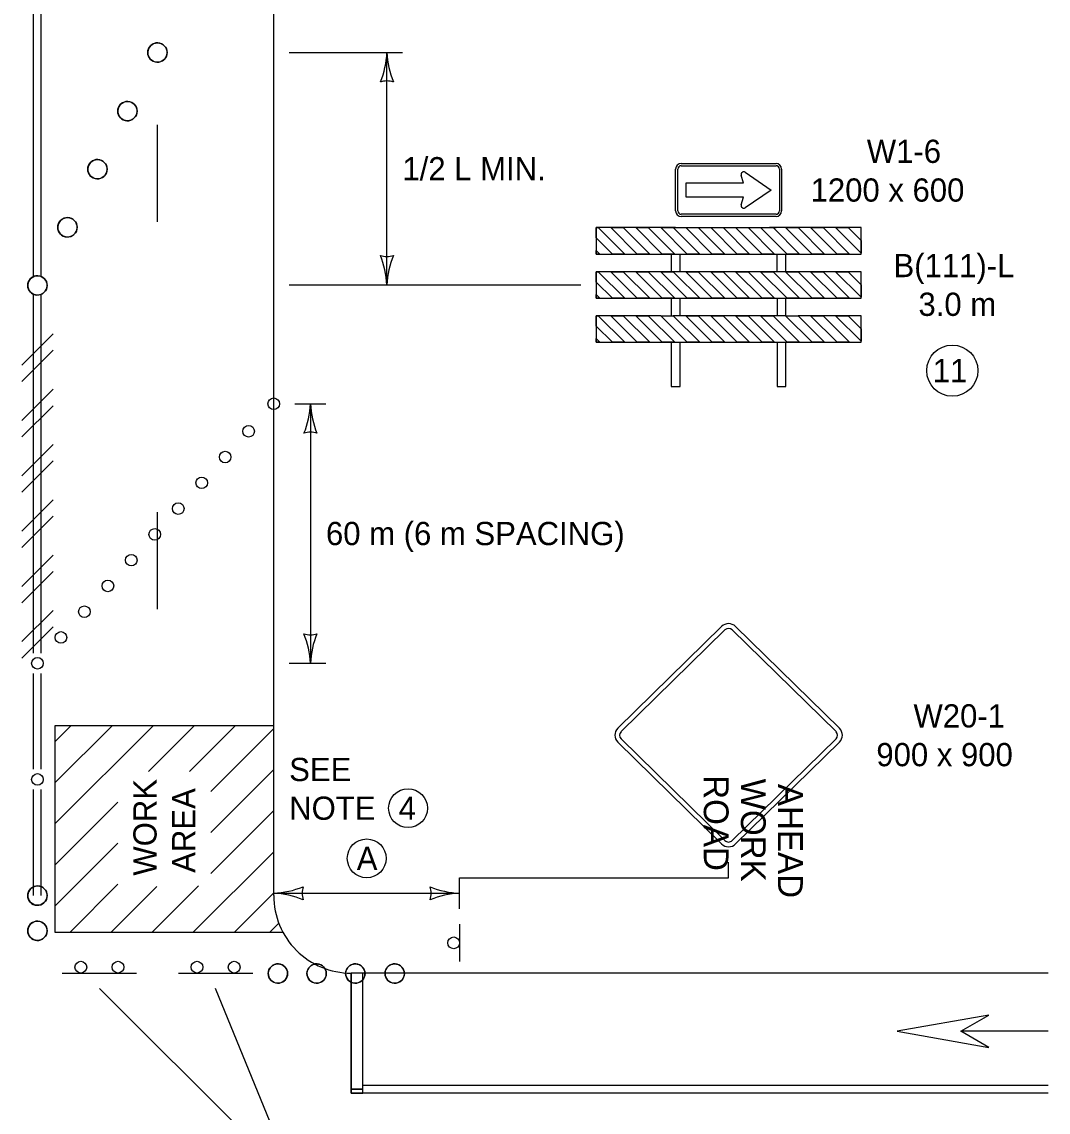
# Model space of a CAD drawing. Extents: x 49991.4 to 50021, y 49987.6 to 50011.4.
# Drawn here: x 50010.553 to 50013.203, y 49993.381 to 49996.197 of the extents above; entities that cross this region are included whole.
import ezdxf

# ---------------------------------------------------------------- set-up
doc = ezdxf.new("R2010")
doc.units = 0
for name, color, linetype in [('Level 1', 7, 'Continuous'), ('Level 2', 7, 'Continuous'), ('Level 3', 7, 'Continuous')]:
    doc.layers.add(name, color=color, linetype=linetype)

# ---------------------------------------------------------------- blocks, each defined once
blk = doc.blocks.new('ARR')
at = {"layer": 'Level 3'}
for centre, radius, start, end in [((1.53, 37.02), 37.05, 247.456, 267.6395), ((-21.37, 0), 9.13, 342.1388, 17.8612), ((1.92, -38.79), 38.83, 92.8273, 112.0772)]:
    blk.add_arc(centre, radius, start, end, dxfattribs=at)

msp = doc.modelspace()

# ---------------------------------------------------------------- linework, layer by layer
at = {"layer": 'Level 1'}
for p, q in [((50011.2032, 49993.9404), (50011.2032, 49998.6295)), ((50010.5832, 49995.5402), (50010.5832, 49996.4525)), ((50010.6032, 49995.5402), (50010.6032, 49996.4525)), ((50010.9033, 49995.6804), (50010.9033, 49995.9304)), ((50012.2411, 49995.7082), (50012.2411, 49995.8165)), ((50012.2468, 49995.7082), (50012.2468, 49995.8165)), ((50012.2554, 49995.8307), (50012.5004, 49995.8307)), ((50012.2554, 49995.825), (50012.5004, 49995.825)), ((50012.509, 49995.8165), (50012.509, 49995.7082)), ((50012.5147, 49995.8165), (50012.5147, 49995.7082)), ((50012.4168, 49995.7806), (50012.4104, 49995.8002)), ((50012.4209, 49995.808), (50012.4874, 49995.7623)), ((50012.2684, 49995.7441), (50012.2684, 49995.7806)), ((50012.2684, 49995.7806), (50012.4168, 49995.7806)), ((50012.4874, 49995.7623), (50012.4209, 49995.7166)), ((50012.4066, 49995.7441), (50012.2684, 49995.7441)), ((50012.4168, 49995.7441), (50012.4066, 49995.7441)), ((50012.4104, 49995.7245), (50012.4168, 49995.7441)), ((50012.5004, 49995.6996), (50012.2554, 49995.6996)), ((50012.5004, 49995.6939), (50012.2554, 49995.6939)), ((50012.1099, 49995.597), (50012.0415, 49995.6654)), ((50012.0415, 49995.6654), (50012.1099, 49995.597)), ((50012.1422, 49995.597), (50012.0738, 49995.6654)), ((50012.1422, 49995.597), (50012.0738, 49995.6654)), ((50012.1744, 49995.597), (50012.106, 49995.6654)), ((50012.106, 49995.6654), (50012.1744, 49995.597)), ((50012.2066, 49995.597), (50012.1382, 49995.6654)), ((50012.2066, 49995.597), (50012.1382, 49995.6654)), ((50012.2389, 49995.597), (50012.1705, 49995.6654)), ((50012.1705, 49995.6654), (50012.2389, 49995.597)), ((50012.2712, 49995.597), (50012.2028, 49995.6654)), ((50012.3034, 49995.597), (50012.235, 49995.6654)), ((50012.235, 49995.6654), (50012.2749, 49995.6654)), ((50012.2554, 49995.6654), (50012.5004, 49995.6654)), ((50012.3356, 49995.597), (50012.2672, 49995.6654)), ((50012.3678, 49995.597), (50012.2994, 49995.6654)), ((50012.4, 49995.597), (50012.3316, 49995.6654)), ((50012.4322, 49995.597), (50012.3638, 49995.6654)), ((50012.4644, 49995.597), (50012.396, 49995.6654)), ((50012.4966, 49995.597), (50012.4282, 49995.6654)), ((50012.529, 49995.597), (50012.4606, 49995.6654)), ((50012.5147, 49995.6654), (50012.4834, 49995.6654)), ((50012.5613, 49995.597), (50012.4929, 49995.6654)), ((50012.5935, 49995.597), (50012.5251, 49995.6654)), ((50012.5935, 49995.597), (50012.5251, 49995.6654)), ((50012.6257, 49995.597), (50012.5573, 49995.6654)), ((50012.5573, 49995.6654), (50012.6257, 49995.597)), ((50012.658, 49995.597), (50012.5896, 49995.6654)), ((50012.658, 49995.597), (50012.5896, 49995.6654)), ((50012.6902, 49995.597), (50012.6218, 49995.6654)), ((50012.6218, 49995.6654), (50012.6902, 49995.597)), ((50012.7199, 49995.5996), (50012.654, 49995.6654)), ((50012.7199, 49995.5996), (50012.654, 49995.6654)), ((50012.7199, 49995.6319), (50012.6863, 49995.6654)), ((50012.6863, 49995.6654), (50012.7199, 49995.6319)), ((50012.0777, 49995.597), (50012.0359, 49995.6388)), ((50012.0777, 49995.597), (50012.0359, 49995.6388)), ((50012.0455, 49995.597), (50012.0359, 49995.6065)), ((50012.0359, 49995.6065), (50012.0455, 49995.597)), ((50012.2525, 49995.5515), (50012.2525, 49995.597)), ((50012.5033, 49995.5515), (50012.5033, 49995.597)), ((50012.1099, 49995.4831), (50012.0415, 49995.5515)), ((50012.0415, 49995.5515), (50012.1099, 49995.4831)), ((50012.1422, 49995.4831), (50012.0738, 49995.5515)), ((50012.1422, 49995.4831), (50012.0738, 49995.5515)), ((50012.1744, 49995.4831), (50012.106, 49995.5515)), ((50012.106, 49995.5515), (50012.1744, 49995.4831)), ((50012.2066, 49995.4831), (50012.1382, 49995.5515)), ((50012.2066, 49995.4831), (50012.1382, 49995.5515)), ((50012.2389, 49995.4831), (50012.1705, 49995.5515)), ((50012.1705, 49995.5515), (50012.2389, 49995.4831)), ((50012.2411, 49995.5131), (50012.2028, 49995.5515)), ((50012.2411, 49995.5453), (50012.235, 49995.5515)), ((50012.3034, 49995.4831), (50012.2411, 49995.5453)), ((50012.3356, 49995.4831), (50012.2672, 49995.5515)), ((50012.3678, 49995.4831), (50012.2994, 49995.5515)), ((50012.4001, 49995.4831), (50012.3317, 49995.5515)), ((50012.4323, 49995.4831), (50012.3639, 49995.5515)), ((50012.4645, 49995.4831), (50012.3961, 49995.5515)), ((50012.4968, 49995.4831), (50012.4284, 49995.5515)), ((50012.529, 49995.4831), (50012.4606, 49995.5515)), ((50012.5613, 49995.4831), (50012.4929, 49995.5515)), ((50012.5935, 49995.4831), (50012.5251, 49995.5515)), ((50012.5935, 49995.4831), (50012.5251, 49995.5515)), ((50012.6257, 49995.4831), (50012.5573, 49995.5515)), ((50012.5573, 49995.5515), (50012.6257, 49995.4831)), ((50012.658, 49995.4831), (50012.5896, 49995.5515)), ((50012.658, 49995.4831), (50012.5896, 49995.5515)), ((50012.6902, 49995.4831), (50012.6218, 49995.5515)), ((50012.6218, 49995.5515), (50012.6902, 49995.4831)), ((50012.7199, 49995.4857), (50012.654, 49995.5515)), ((50012.7199, 49995.4857), (50012.654, 49995.5515)), ((50012.7199, 49995.5179), (50012.6863, 49995.5515)), ((50012.6863, 49995.5515), (50012.7199, 49995.5179)), ((50012.0777, 49995.4831), (50012.0359, 49995.5248)), ((50012.0777, 49995.4831), (50012.0359, 49995.5248)), ((50012.2712, 49995.4831), (50012.2411, 49995.5131)), ((50010.5832, 49994.5666), (50010.5832, 49995.4931)), ((50010.6032, 49994.5666), (50010.6032, 49995.4931)), ((50012.0455, 49995.4831), (50012.0359, 49995.4926)), ((50012.0359, 49995.4926), (50012.0455, 49995.4831)), ((50012.1099, 49995.3692), (50012.0415, 49995.4376)), ((50012.0415, 49995.4376), (50012.1099, 49995.3692)), ((50012.1422, 49995.3692), (50012.0738, 49995.4376)), ((50012.1422, 49995.3692), (50012.0738, 49995.4376)), ((50012.1744, 49995.3692), (50012.106, 49995.4376)), ((50012.106, 49995.4376), (50012.1744, 49995.3692)), ((50012.2066, 49995.3692), (50012.1382, 49995.4376)), ((50012.2066, 49995.3692), (50012.1382, 49995.4376)), ((50012.2389, 49995.3692), (50012.1705, 49995.4376)), ((50012.1705, 49995.4376), (50012.2389, 49995.3692)), ((50012.2712, 49995.3692), (50012.2028, 49995.4376)), ((50012.2712, 49995.3692), (50012.2028, 49995.4376)), ((50012.3034, 49995.3692), (50012.235, 49995.4376)), ((50012.235, 49995.4376), (50012.3034, 49995.3692)), ((50012.3356, 49995.3692), (50012.2672, 49995.4376)), ((50012.3356, 49995.3692), (50012.2672, 49995.4376)), ((50012.3678, 49995.3692), (50012.2994, 49995.4376)), ((50012.2994, 49995.4376), (50012.3678, 49995.3692)), ((50012.4001, 49995.3692), (50012.3317, 49995.4376)), ((50012.4001, 49995.3692), (50012.3317, 49995.4376)), ((50012.4323, 49995.3692), (50012.3639, 49995.4376)), ((50012.3639, 49995.4376), (50012.4323, 49995.3692)), ((50012.4645, 49995.3692), (50012.3961, 49995.4376)), ((50012.4645, 49995.3692), (50012.3961, 49995.4376)), ((50012.4968, 49995.3692), (50012.4284, 49995.4376)), ((50012.4284, 49995.4376), (50012.4968, 49995.3692)), ((50012.529, 49995.3692), (50012.4606, 49995.4376)), ((50012.529, 49995.3692), (50012.4606, 49995.4376)), ((50012.5613, 49995.3692), (50012.4929, 49995.4376)), ((50012.4929, 49995.4376), (50012.5613, 49995.3692)), ((50012.5935, 49995.3692), (50012.5251, 49995.4376)), ((50012.5935, 49995.3692), (50012.5251, 49995.4376)), ((50012.6257, 49995.3692), (50012.5573, 49995.4376)), ((50012.5573, 49995.4376), (50012.6257, 49995.3692)), ((50012.658, 49995.3692), (50012.5896, 49995.4376)), ((50012.658, 49995.3692), (50012.5896, 49995.4376)), ((50012.6902, 49995.3692), (50012.6218, 49995.4376)), ((50012.6218, 49995.4376), (50012.6902, 49995.3692)), ((50012.7199, 49995.3717), (50012.654, 49995.4376)), ((50012.7199, 49995.3717), (50012.654, 49995.4376)), ((50012.7199, 49995.4039), (50012.6863, 49995.4376)), ((50012.6863, 49995.4376), (50012.7199, 49995.4039)), ((50010.5528, 49995.3104), (50010.6336, 49995.3912)), ((50012.0777, 49995.3692), (50012.0359, 49995.4109)), ((50012.0777, 49995.3692), (50012.0359, 49995.4109)), ((50012.0455, 49995.3692), (50012.0359, 49995.3787)), ((50012.0359, 49995.3787), (50012.0455, 49995.3692)), ((50010.5528, 49995.2676), (50010.6336, 49995.3484)), ((50010.5528, 49995.1676), (50010.6336, 49995.2484)), ((50010.5528, 49995.1247), (50010.6336, 49995.2055)), ((50010.5528, 49995.0247), (50010.6336, 49995.1055)), ((50010.5528, 49994.9819), (50010.6336, 49995.0627)), ((50010.5528, 49994.8819), (50010.6336, 49994.9627)), ((50010.5528, 49994.839), (50010.6336, 49994.9198)), ((50010.9033, 49994.6804), (50010.9033, 49994.9304)), ((50010.5528, 49994.739), (50010.6336, 49994.8198)), ((50010.5528, 49994.6962), (50010.6336, 49994.777)), ((50010.5528, 49994.5962), (50010.6336, 49994.677)), ((50010.5528, 49994.5533), (50010.6336, 49994.6341)), ((50012.0917, 49994.3726), (50012.3599, 49994.6354)), ((50012.3958, 49994.6354), (50012.6641, 49994.3726)), ((50012.1003, 49994.3638), (50012.3685, 49994.6266)), ((50012.3872, 49994.6266), (50012.6555, 49994.3638)), ((50010.5832, 49994.2666), (50010.5832, 49994.5142)), ((50010.6032, 49994.2666), (50010.6032, 49994.5142)), ((50011.2032, 49994.3789), (50010.6384, 49994.3789)), ((50010.6384, 49994.3789), (50010.6384, 49993.8464)), ((50010.6384, 49994.3377), (50010.6796, 49994.3789)), ((50010.6384, 49994.2316), (50010.7857, 49994.3789)), ((50010.6384, 49994.1255), (50010.8918, 49994.3789)), ((50010.88, 49994.2611), (50010.9978, 49994.3789)), ((50010.9861, 49994.2611), (50011.1039, 49994.3789)), ((50011.0408, 49994.2097), (50011.2032, 49994.3721)), ((50012.3599, 49994.0738), (50012.0917, 49994.3366)), ((50012.3685, 49994.0826), (50012.1003, 49994.3454)), ((50012.6555, 49994.3454), (50012.3872, 49994.0826)), ((50012.6641, 49994.3366), (50012.3958, 49994.0738)), ((50011.0408, 49994.1037), (50011.2032, 49994.2661)), ((50010.5832, 49993.9404), (50010.5832, 49994.2142)), ((50010.6032, 49993.9404), (50010.6032, 49994.2142)), ((50010.6384, 49994.0195), (50010.8008, 49994.1819)), ((50011.0408, 49993.9976), (50011.2032, 49994.16)), ((50010.6384, 49993.9134), (50010.8008, 49994.0758)), ((50010.9957, 49993.8464), (50011.2032, 49994.0539)), ((50010.6775, 49993.8464), (50010.8008, 49993.9697)), ((50010.7836, 49993.8464), (50010.9014, 49993.9643)), ((50010.8896, 49993.8464), (50011.0091, 49993.9659)), ((50011.1017, 49993.8464), (50011.2032, 49993.9479)), ((50010.6384, 49993.8464), (50011.2266, 49993.8464)), ((50011.1936, 49993.8464), (50011.2163, 49993.8691)), ((50011.6832, 49993.8665), (50011.6832, 49993.7705)), ((50010.6572, 49993.7405), (50010.7532, 49993.7405)), ((50010.7532, 49993.7405), (50010.8492, 49993.7405)), ((50010.9572, 49993.7405), (50011.0532, 49993.7405)), ((50011.0532, 49993.7405), (50011.1492, 49993.7405)), ((50013.2032, 49993.7404), (50011.4032, 49993.7404)), ((50011.4032, 49993.4304), (50011.4032, 49993.7404)), ((50011.4332, 49993.4304), (50011.4332, 49993.7404)), ((50013.2032, 49993.5905), (50012.9773, 49993.5905)), ((50013.2032, 49993.5901), (50012.9773, 49993.5901)), ((50013.2032, 49993.4504), (50011.4332, 49993.4504)), ((50011.4332, 49993.4405), (50011.4032, 49993.4405)), ((50013.2032, 49993.4304), (50011.4032, 49993.4304))]:
    msp.add_line(p, q, dxfattribs=at)
for points in [[(50012.2411, 49995.6654), (50012.0359, 49995.6654), (50012.0359, 49995.597), (50012.2411, 49995.597)], [(50012.0359, 49995.6388), (50012.0359, 49995.6654), (50012.0415, 49995.6654)], [(50012.0738, 49995.6654), (50012.106, 49995.6654)], [(50012.1382, 49995.6654), (50012.1705, 49995.6654)], [(50012.3034, 49995.597), (50012.2712, 49995.597), (50012.2028, 49995.6654), (50012.235, 49995.6654), (50012.3034, 49995.597)], [(50012.2411, 49995.597), (50012.7199, 49995.597), (50012.7199, 49995.6654), (50012.5147, 49995.6654)], [(50012.2672, 49995.6654), (50012.2749, 49995.6654), (50012.2994, 49995.6654), (50012.3678, 49995.597), (50012.3356, 49995.597), (50012.2672, 49995.6654)], [(50012.3316, 49995.6654), (50012.3638, 49995.6654), (50012.4322, 49995.597), (50012.4, 49995.597), (50012.3316, 49995.6654)], [(50012.396, 49995.6654), (50012.4282, 49995.6654), (50012.4966, 49995.597), (50012.4644, 49995.597), (50012.396, 49995.6654)], [(50012.4606, 49995.6654), (50012.4834, 49995.6654), (50012.4929, 49995.6654), (50012.5613, 49995.597), (50012.529, 49995.597), (50012.4606, 49995.6654)], [(50012.5251, 49995.6654), (50012.5573, 49995.6654)], [(50012.5896, 49995.6654), (50012.6218, 49995.6654)], [(50012.654, 49995.6654), (50012.6863, 49995.6654)], [(50012.7199, 49995.6319), (50012.7199, 49995.5996)], [(50012.0455, 49995.597), (50012.0359, 49995.597), (50012.0359, 49995.6065)], [(50012.1099, 49995.597), (50012.0777, 49995.597)], [(50012.1744, 49995.597), (50012.1422, 49995.597)], [(50012.2389, 49995.597), (50012.2066, 49995.597)], [(50012.2297, 49995.597), (50012.2297, 49995.5515)], [(50012.5261, 49995.5514), (50012.5261, 49995.597)], [(50012.6257, 49995.597), (50012.5935, 49995.597)], [(50012.6902, 49995.597), (50012.658, 49995.597)], [(50012.2411, 49995.5515), (50012.0359, 49995.5515), (50012.0359, 49995.4831), (50012.7199, 49995.4831), (50012.7199, 49995.5515), (50012.2411, 49995.5515)], [(50012.0359, 49995.5248), (50012.0359, 49995.5515), (50012.0415, 49995.5515)], [(50012.0738, 49995.5515), (50012.106, 49995.5515)], [(50012.1382, 49995.5515), (50012.1705, 49995.5515)], [(50012.3034, 49995.4831), (50012.2712, 49995.4831), (50012.2411, 49995.5131), (50012.2028, 49995.5515), (50012.2297, 49995.5515), (50012.235, 49995.5515), (50012.2411, 49995.5453), (50012.3034, 49995.4831)], [(50012.2672, 49995.5515), (50012.2994, 49995.5515), (50012.3678, 49995.4831), (50012.3356, 49995.4831), (50012.2672, 49995.5515)], [(50012.3317, 49995.5515), (50012.3639, 49995.5515), (50012.4323, 49995.4831), (50012.4001, 49995.4831), (50012.3317, 49995.5515)], [(50012.3961, 49995.5515), (50012.4284, 49995.5515), (50012.4968, 49995.4831), (50012.4645, 49995.4831), (50012.3961, 49995.5515)], [(50012.4606, 49995.5515), (50012.4929, 49995.5515), (50012.5613, 49995.4831), (50012.529, 49995.4831), (50012.4606, 49995.5515)], [(50012.5251, 49995.5515), (50012.5573, 49995.5515)], [(50012.5896, 49995.5515), (50012.6218, 49995.5515)], [(50012.654, 49995.5515), (50012.6863, 49995.5515)], [(50012.7199, 49995.5179), (50012.7199, 49995.4857)], [(50012.0455, 49995.4831), (50012.0359, 49995.4831), (50012.0359, 49995.4926)], [(50012.1099, 49995.4831), (50012.0777, 49995.4831)], [(50012.1744, 49995.4831), (50012.1422, 49995.4831)], [(50012.2389, 49995.4831), (50012.2066, 49995.4831)], [(50012.2297, 49995.4831), (50012.2297, 49995.4376)], [(50012.2525, 49995.4376), (50012.2525, 49995.4831)], [(50012.5033, 49995.4831), (50012.5033, 49995.4376)], [(50012.5261, 49995.4376), (50012.5261, 49995.4831)], [(50012.6257, 49995.4831), (50012.5935, 49995.4831)], [(50012.6902, 49995.4831), (50012.658, 49995.4831)], [(50012.0359, 49995.4109), (50012.0359, 49995.4376), (50012.0415, 49995.4376)], [(50012.2028, 49995.4376), (50012.0359, 49995.4376), (50012.0359, 49995.3692), (50012.7199, 49995.3692), (50012.7199, 49995.4376), (50012.5573, 49995.4376)], [(50012.0738, 49995.4376), (50012.106, 49995.4376)], [(50012.1382, 49995.4376), (50012.1705, 49995.4376)], [(50012.2028, 49995.4376), (50012.235, 49995.4376)], [(50012.5251, 49995.4376), (50012.235, 49995.4376)], [(50012.2672, 49995.4376), (50012.2994, 49995.4376)], [(50012.3317, 49995.4376), (50012.3639, 49995.4376)], [(50012.3961, 49995.4376), (50012.4284, 49995.4376)], [(50012.4606, 49995.4376), (50012.4929, 49995.4376)], [(50012.5251, 49995.4376), (50012.5573, 49995.4376)], [(50012.5896, 49995.4376), (50012.6218, 49995.4376)], [(50012.654, 49995.4376), (50012.6863, 49995.4376)], [(50012.7199, 49995.4039), (50012.7199, 49995.3717)], [(50012.0455, 49995.3692), (50012.0359, 49995.3692), (50012.0359, 49995.3787)], [(50012.1099, 49995.3692), (50012.0777, 49995.3692)], [(50012.1744, 49995.3692), (50012.1422, 49995.3692)], [(50012.2389, 49995.3692), (50012.2066, 49995.3692)], [(50012.2297, 49995.369), (50012.2297, 49995.2551), (50012.2525, 49995.2551), (50012.2525, 49995.369)], [(50012.3034, 49995.3692), (50012.2712, 49995.3692)], [(50012.3678, 49995.3692), (50012.3356, 49995.3692)], [(50012.4323, 49995.3692), (50012.4001, 49995.3692)], [(50012.4968, 49995.3692), (50012.4645, 49995.3692)], [(50012.5033, 49995.369), (50012.5033, 49995.2551), (50012.5261, 49995.2551), (50012.5261, 49995.369)], [(50012.5613, 49995.3692), (50012.529, 49995.3692)], [(50012.6257, 49995.3692), (50012.5935, 49995.3692)], [(50012.6902, 49995.3692), (50012.658, 49995.3692)], [(50011.4332, 49993.7404), (50011.4032, 49993.7404), (50011.4032, 49993.4405), (50011.4332, 49993.4405), (50011.4332, 49993.7404)], [(50011.4032, 49993.4405), (50011.4032, 49993.4304), (50011.4332, 49993.4304), (50011.4332, 49993.4405), (50011.4032, 49993.4405)]]:
    msp.add_lwpolyline(points, dxfattribs=at)
msp.add_lwpolyline([(50013.0496, 49993.6321), (50012.8131, 49993.5905), (50013.0496, 49993.5485), (50012.9774, 49993.5905)], close=True, dxfattribs=at)
for centre, radius in [((50010.903, 49996.1173), 0.025), ((50010.8256, 49995.966), 0.025), ((50010.7481, 49995.816), 0.025), ((50010.6706, 49995.666), 0.025), ((50010.5932, 49995.516), 0.025), ((50011.2032, 49995.2104), 0.015), ((50011.1385, 49995.1394), 0.015), ((50011.0779, 49995.0728), 0.015), ((50011.0173, 49995.0063), 0.015), ((50010.9567, 49994.9397), 0.015), ((50010.8961, 49994.8732), 0.015), ((50010.8355, 49994.8066), 0.015), ((50010.775, 49994.7401), 0.015), ((50010.7144, 49994.6735), 0.015), ((50010.6538, 49994.607), 0.015), ((50010.5932, 49994.5404), 0.015), ((50010.5932, 49994.2404), 0.015), ((50010.5932, 49993.9404), 0.025), ((50010.5932, 49993.8496), 0.025), ((50011.668, 49993.8185), 0.0152), ((50010.7052, 49993.7557), 0.0152), ((50010.8012, 49993.7557), 0.0152), ((50011.0052, 49993.7557), 0.0152), ((50011.1012, 49993.7557), 0.0152), ((50011.2141, 49993.7392), 0.025), ((50011.3141, 49993.7392), 0.025), ((50011.414, 49993.7392), 0.025), ((50011.5157, 49993.7392), 0.025)]:
    msp.add_circle(centre, radius, dxfattribs=at)
for centre, radius, start, end in [((50010.903, 49996.1173), 0.025, 357.0759, 177.0759), ((50010.903, 49996.1173), 0.025, 177.0759, 357.0759), ((50010.8256, 49995.966), 0.025, 357.0759, 177.0759), ((50010.8256, 49995.966), 0.025, 177.0759, 357.0759), ((50010.7481, 49995.816), 0.025, 177.0759, 357.0759), ((50010.7481, 49995.816), 0.025, 357.0759, 177.0759), ((50012.2554, 49995.8165), 0.0142, 90, 180), ((50012.2554, 49995.8165), 0.00855, 90, 180), ((50012.5004, 49995.8165), 0.0142, 0, 90), ((50012.5004, 49995.8165), 0.00855, 0, 90), ((50012.417, 49995.8023), 0.00695, 55.4806, 197.9582), ((50012.2554, 49995.7082), 0.0142, 180, 270), ((50012.2554, 49995.7082), 0.00855, 180, 270), ((50012.417, 49995.7224), 0.00695, 162.0418, 304.5194), ((50012.5004, 49995.7082), 0.0142, 270, 0), ((50012.5004, 49995.7082), 0.00855, 270, 0), ((50010.6706, 49995.666), 0.025, 357.0759, 177.0759), ((50010.6706, 49995.666), 0.025, 177.0759, 357.0759), ((50010.5932, 49995.516), 0.025, 357.0759, 177.0759), ((50010.5932, 49995.516), 0.025, 177.0759, 357.0759), ((50010.5932, 49993.9404), 0.025, 357.0759, 177.0759), ((50010.5932, 49993.9404), 0.025, 177.0759, 357.0759), ((50011.4032, 49993.9404), 0.2, 180, 270.0006), ((50010.5932, 49993.8496), 0.025, 357.0759, 177.0759), ((50010.5932, 49993.8496), 0.025, 177.0759, 357.0759), ((50011.2141, 49993.7392), 0.025, 357.0759, 177.0759), ((50011.3141, 49993.7392), 0.025, 357.0759, 177.0759), ((50011.414, 49993.7392), 0.025, 357.0759, 177.0759), ((50011.5157, 49993.7392), 0.025, 357.0759, 177.0759), ((50011.2141, 49993.7392), 0.025, 177.0759, 357.0759), ((50011.3141, 49993.7392), 0.025, 177.0759, 357.0759), ((50011.414, 49993.7392), 0.025, 177.0759, 357.0759), ((50011.5157, 49993.7392), 0.025, 177.0759, 357.0759)]:
    msp.add_arc(centre, radius, start, end, dxfattribs=at)
for centre, major_axis, ratio, start_param, end_param in [((50012.3779, 49994.6175), (-0.0255, 0), 0.98963, 3.926991, 5.497787), ((50012.3779, 49994.6175), (-0.0132, 0), 0.98, 3.926991, 5.497787), ((50012.1097, 49994.3546), (-0.0255, 0), 0.98963, 5.497787, 7.068583), ((50012.1097, 49994.3546), (-0.0132, 0), 0.98, 5.497787, 7.068583), ((50012.6461, 49994.3546), (0.0132, 0), 0.98, 5.497795, 7.068583), ((50012.6461, 49994.3546), (0.0255, 0), 0.98963, 5.497795, 7.068583), ((50012.3779, 49994.0918), (-0.0255, 0), 0.98963, 0.785394, 2.356194), ((50012.3779, 49994.0918), (-0.0132, 0), 0.98, 0.785394, 2.356194)]:
    msp.add_ellipse(centre, major_axis=major_axis, ratio=ratio, start_param=start_param, end_param=end_param, dxfattribs=at)
at = {"layer": 'Level 2'}
for centre, radius in [((50012.9556, 49995.2959), 0.0662), ((50011.5501, 49994.1662), 0.0501), ((50011.4434, 49994.0366), 0.0501)]:
    msp.add_circle(centre, radius, dxfattribs=at)
at = {"layer": 'Level 3'}
for p, q in [((50011.2432, 49996.1173), (50011.5356, 49996.1173)), ((50011.2432, 49995.5173), (50011.9959, 49995.5173)), ((50011.2582, 49995.2104), (50011.3382, 49995.2104)), ((50011.2982, 49995.2104), (50011.2982, 49994.5404)), ((50011.2432, 49994.5404), (50011.3382, 49994.5404)), ((50011.6832, 49993.9065), (50011.6832, 49993.9865)), ((50011.2032, 49993.9465), (50011.6832, 49993.9465)), ((50011.2601, 49993.1959), (50010.7532, 49993.7005)), ((50011.2601, 49993.1959), (50011.0532, 49993.7005))]:
    msp.add_line(p, q, dxfattribs=at)
for points in [[(50011.4556, 49995.5173), (50011.4956, 49995.5173), (50011.4956, 49996.1173)], [(50011.6832, 49993.9865), (50012.3779, 49993.9865), (50012.3779, 49994.0265)]]:
    msp.add_lwpolyline(points, dxfattribs=at)

# ---------------------------------------------------------------- block references
at = {"layer": 'Level 2', "xscale": 0.006, "yscale": 0.006}
for p, rotation in [((50011.4956, 49995.5173), -90), ((50011.2032, 49993.9465), -179.9999999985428), ((50011.6832, 49993.9465), 1.457212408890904e-09)]:
    msp.add_blockref('ARR', p, dxfattribs=dict(at, rotation=rotation))
at = {"layer": 'Level 3', "xscale": 0.006, "yscale": 0.006}
for p, rotation in [((50011.4956, 49996.1173), 90), ((50011.2982, 49995.2104), 90), ((50011.2982, 49994.5404), -90)]:
    msp.add_blockref('ARR', p, dxfattribs=dict(at, rotation=rotation))

# ---------------------------------------------------------------- texts
at = {"layer": 'Level 1'}
for s, p in [('ROAD', (50012.3139, 49994.2514)), ('WORK', (50012.4098, 49994.2424)), ('AHEAD', (50012.5057, 49994.2288))]:
    msp.add_text(s, height=0.06395, rotation=270, dxfattribs=at).set_placement(p)
at = {"layer": 'Level 2'}
for s, height, p in [('W1-6', 0.06, (50012.7348, 49995.8323)), ('1/2 L MIN.', 0.06, (50011.5356, 49995.7873)), ('1200 x 600', 0.06, (50012.5897, 49995.7323)), ('B(111)-L', 0.06, (50012.8037, 49995.5373)), ('3.0 m', 0.06, (50012.8682, 49995.4373)), ('11', 0.06006, (50012.905, 49995.266)), ('60 m (6 m SPACING)', 0.06, (50011.3382, 49994.8454)), ('SEE', 0.06, (50011.2432, 49994.2362)), ('NOTE', 0.06, (50011.2432, 49994.1362)), ('4', 0.06, (50011.5261, 49994.1362))]:
    msp.add_text(s, height=height, dxfattribs=at).set_placement(p)
for s, rotation, p in [('W20-1', 360, (50012.8553, 49994.3745)), ('900 x 900', 360, (50012.7594, 49994.2745)), ('WORK', 90, (50010.9008, 49993.992)), ('AREA', 90, (50011.0008, 49993.9994)), ('A', 0, (50011.4177, 49994.0066))]:
    msp.add_text(s, height=0.06, rotation=rotation, dxfattribs=at).set_placement(p)

doc.saveas('drawing.dxf')
